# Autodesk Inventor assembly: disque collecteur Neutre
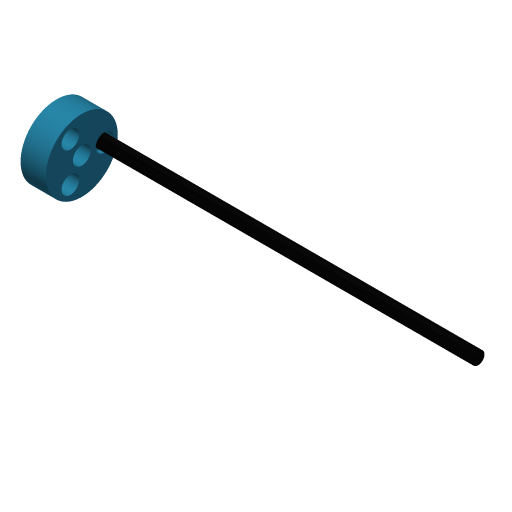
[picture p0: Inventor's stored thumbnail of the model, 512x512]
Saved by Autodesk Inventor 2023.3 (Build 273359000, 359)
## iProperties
Created: 2017-03
Part Number: disque collecteur Neutre
Document SubType Name: Assembly
Designer: thierry.jost
Author: thierry.jost
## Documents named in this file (3)
- C:\Travail\BTS TechCom\2-TechnoIndus\21-Meca\214-Systémes Industriels-SI\2141-Pièces Ecrites\21411-Cycle1\214112-TP02Eolienne\2141122-DossierTechniqueEolienne\21411223-Maquette numerique\CEC-Eolienne\Disque collecteur\20n-Disque collecteur Neutre.iam
- C:\Travail\BTS TechCom\2-TechnoIndus\21-Meca\214-Systémes Industriels-SI\2141-Pièces Ecrites\21411-Cycle1\214112-TP02Eolienne\2141122-DossierTechniqueEolienne\21411223-Maquette numerique\CEC-Eolienne\Disque collecteur\Disque collecteur n.ipt
- C:\Travail\BTS TechCom\2-TechnoIndus\21-Meca\214-Systémes Industriels-SI\2141-Pièces Ecrites\21411-Cycle1\214112-TP02Eolienne\2141122-DossierTechniqueEolienne\21411223-Maquette numerique\CEC-Eolienne\Disque collecteur\neutre.ipt
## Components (2 placed, 2 different names)
1. Disque collecteur n:1 — Insert:1
2. neutre:1 — Insert:1
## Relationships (1: Insert 1)
- Insert:1: Disque collecteur n:1 ↔ neutre:1
